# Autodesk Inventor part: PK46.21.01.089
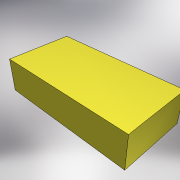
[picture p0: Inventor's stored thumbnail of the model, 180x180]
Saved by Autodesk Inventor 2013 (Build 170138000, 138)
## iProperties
Created: 2007-06
Part Number: PK46.21.01.089
Material: Steel, Mild
Document SubType Name: Modeling
Designer: SAlex
Density: 7.86 g/cm^3
Mass: 4024.32 g
Surface Area: 448 cm^2
Volume: 512 cm^3
Author: SAlex
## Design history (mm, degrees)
sketch "Sketch1"
  geometry: L1 (0, 0)-(160, 0); L2 (160, 0)-(160, 80); L3 (160, 80)-(0, 80); L4 (0, 80)-(0, 0)
  constraints: 8 end point, 2 parallel, 1 horizontal, 1 perpendicular, 1 other
  dimensions: "d0" = 160 distance of L1.start L1.end; "d1" = 80 distance of L3.end L1.start
extrude "Extrusion1" new body sketch "Sketch1" distance "d2" = 40; taper "d3" = 0 deg
body "Solid1"
